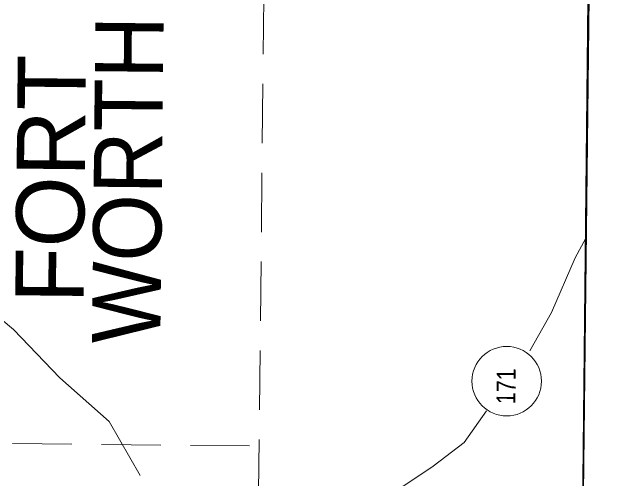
# Model space of a CAD drawing. Extents: x 2356576 to 2377878, y 6966390 to 6990634.
# Drawn here: x 2366013.1 to 2366226.3, y 6968758.5 to 6968926.1 of the extents above; entities that cross this region are included whole.
import ezdxf

# ---------------------------------------------------------------- set-up
doc = ezdxf.new("R2010")
doc.units = 0
doc.header["$LTSCALE"] = 7.1
doc.linetypes.add('MEDIUM_DASHED', pattern=[4.5, 3, -1.5])
doc.layers.add('19', color=7, linetype='Continuous', lineweight=13)
doc.layers.add('8', color=7, linetype='Continuous', lineweight=13)

msp = doc.modelspace()

# ---------------------------------------------------------------- linework, layer by layer
at = {"layer": '19', "lineweight": 35}
msp.add_line((2366217.375, 6968654.072), (2366226.339, 6969461.286), dxfattribs=at)
at = {"layer": '19', "linetype": 'MEDIUM_DASHED'}
for p, q in [((2366100.797, 6968655.28), (2366107.007, 6969254.676)), ((2365853.647, 6968772.57), (2366101.234, 6968770.037))]:
    msp.add_line(p, q, dxfattribs=at)
at = {"layer": '19'}
for p, q in [((2366032.264, 6968845.88), (2366029.566, 6968843.028)), ((2366207.073, 6968818.024), (2366199.222, 6968804.244)), ((2366175.628, 6968771.367), (2366183.725, 6968782.683)), ((2366048.07, 6968778.809), (2366059.182, 6968759.4)), ((2366164.527, 6968762.841), (2366175.628, 6968771.367))]:
    msp.add_line(p, q, dxfattribs=at)
at = {"layer": '19', "lineweight": 25}
msp.add_lwpolyline([(2365597.072, 6968660.498), (2366217.375, 6968654.072), (2366223.585, 6969253.468), (2365603.282, 6969259.894)], dxfattribs=at)
at = {"layer": '19'}
for points in [[(2366207.073, 6968818.024), (2366215.557, 6968837.709), (2366219.35, 6968844.75)], [(2365993.108, 6968830.981), (2366004.002, 6968819.979), (2366013.699, 6968811.898), (2366030.324, 6968794.501), (2366048.07, 6968778.809)], [(2366022.529, 6968656.091), (2366028.702, 6968661.095), (2366048.435, 6968675.023), (2366071.184, 6968681.148), (2366089.535, 6968686.03), (2366100.837, 6968696.954), (2366119.29, 6968717.043), (2366127.961, 6968728.866), (2366142.017, 6968747.71), (2366164.527, 6968762.841)]]:
    msp.add_lwpolyline(points, dxfattribs=at)
msp.add_circle((2366190.958, 6968793.353), 12.486, dxfattribs=at)
at = {"layer": '8', "lineweight": 35}
msp.add_line((2366217.375, 6968654.072), (2366226.339, 6969461.286), dxfattribs=at)
at = {"layer": '8', "linetype": 'MEDIUM_DASHED'}
for p, q in [((2366100.797, 6968655.28), (2366107.007, 6969254.676)), ((2365853.647, 6968772.57), (2366101.234, 6968770.037))]:
    msp.add_line(p, q, dxfattribs=at)
at = {"layer": '8'}
for p, q in [((2366032.264, 6968845.88), (2366029.566, 6968843.028)), ((2366207.073, 6968818.024), (2366199.222, 6968804.244)), ((2366175.628, 6968771.367), (2366183.725, 6968782.683)), ((2366048.07, 6968778.809), (2366059.182, 6968759.4)), ((2366164.527, 6968762.841), (2366175.628, 6968771.367))]:
    msp.add_line(p, q, dxfattribs=at)
at = {"layer": '8', "lineweight": 25}
msp.add_lwpolyline([(2365597.072, 6968660.498), (2366217.375, 6968654.072), (2366223.585, 6969253.468), (2365603.282, 6969259.894)], dxfattribs=at)
at = {"layer": '8'}
for points in [[(2366207.073, 6968818.024), (2366215.557, 6968837.709), (2366219.35, 6968844.75)], [(2365993.108, 6968830.981), (2366004.002, 6968819.979), (2366013.699, 6968811.898), (2366030.324, 6968794.501), (2366048.07, 6968778.809)], [(2366022.529, 6968656.091), (2366028.702, 6968661.095), (2366048.435, 6968675.023), (2366071.184, 6968681.148), (2366089.535, 6968686.03), (2366100.837, 6968696.954), (2366119.29, 6968717.043), (2366127.961, 6968728.866), (2366142.017, 6968747.71), (2366164.527, 6968762.841)]]:
    msp.add_lwpolyline(points, dxfattribs=at)
msp.add_circle((2366190.958, 6968793.353), 12.486, dxfattribs=at)

# ---------------------------------------------------------------- texts
at = {"layer": '19'}
for s, height, width, p in [('WORTH', 24.52, 0.95, (2366066.453, 6968806.82)), ('171', 6.798, 0.85, (2366194.07, 6968785.036))]:
    msp.add_text(s, height=height, rotation=89.406, dxfattribs=dict(at, width=width)).set_placement(p)
msp.add_text('FORT', height=24.52, rotation=89.406, dxfattribs=at).set_placement((2366038.85, 6968821.298))
at = {"layer": '8'}
for s, height, width, p in [('WORTH', 24.52, 0.95, (2366066.453, 6968806.82)), ('171', 6.798, 0.85, (2366194.07, 6968785.036))]:
    msp.add_text(s, height=height, rotation=89.406, dxfattribs=dict(at, width=width)).set_placement(p)
msp.add_text('FORT', height=24.52, rotation=89.406, dxfattribs=at).set_placement((2366038.85, 6968821.298))

doc.saveas('drawing.dxf')
